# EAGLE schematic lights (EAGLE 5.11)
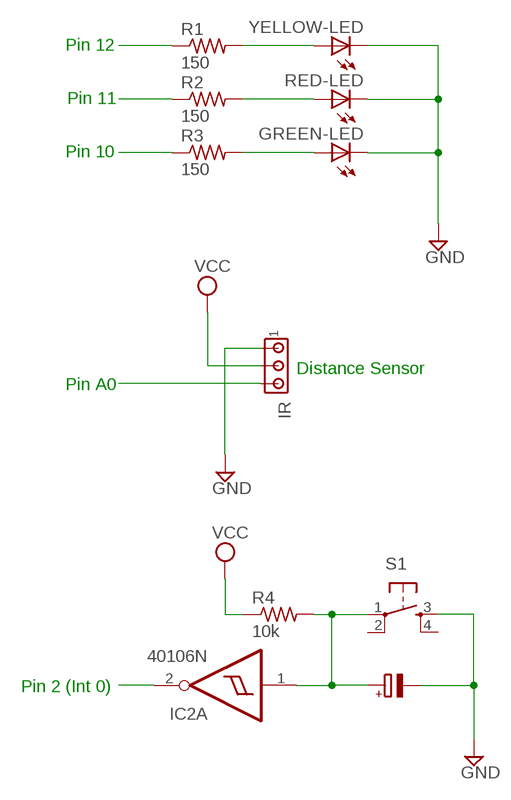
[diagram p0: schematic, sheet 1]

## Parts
GREEN-LED  LAP4-BOTTOM  [P47F-BOTTOM]
IC2  40106N  [DIL14]
IR  MTA03-100  [10X03MTA]
R1  150  RESISTOR-1206  [R1206]
R2  150  RESISTOR-1206  [R1206]
R3  150  RESISTOR-1206  [R1206]
R4  10k  RESISTOR-1206  [R1206]
RED-LED  LAP4-BOTTOM  [P47F-BOTTOM]
S1  TAC_SWITCHSMD  [TACTILE_SWITCH_SMD]
YELLOW-LED  LAP4-BOTTOM  [P47F-BOTTOM]

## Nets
GND: GREEN-LED.C IR.1 RED-LED.C S1.3 YELLOW-LED.C
N$1: R1.1
N$2: R2.1
N$3: R3.1
N$4: GREEN-LED.A R3.2
N$5: R2.2 RED-LED.A
N$6: R1.2 YELLOW-LED.A
N$7: IR.3
N$8: IC2.1(A:I) R4.2 S1.1
N$9: IC2.2(A:O)
VCC: IR.2 R4.1
Unconnected: IC2.3(B:I) IC2.4(B:O) IC2.5(C:I) IC2.6(C:O) IC2.8(D:O) IC2.9(D:I) IC2.10(E:O) IC2.11(E:I) IC2.12(F:O) IC2.13(F:I) S1.2 S1.4

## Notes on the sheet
- Pin 12
- Pin 11
- Pin 10
- Distance Sensor
- Pin A0
- Pin 2 (Int 0)

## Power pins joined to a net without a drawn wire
VDD: IC2.14(P:VDD)
VSS: IC2.7(P:VSS)

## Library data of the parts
GREEN-LED RED-LED YELLOW-LED = led:*P4: PointLED® Enhanced Thinfilm LED TOP & BOTTOM mount
IC2 = 40xx:40106: Hex SCHMITT TRIGGER
IR = con-amp:MTA03-100: AMP connector; OC_FARNELL: unknown; OC_NEWARK: unknown
R1-R4 = Passives:RESISTOR: Resistor
S1 = SparkFun:TAC_SWITCH: Momentary Switch Button commonly used for reset or general input. Spark Fun Electronics SKU : COM-00097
